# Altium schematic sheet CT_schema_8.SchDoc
size 278 x 170 mm
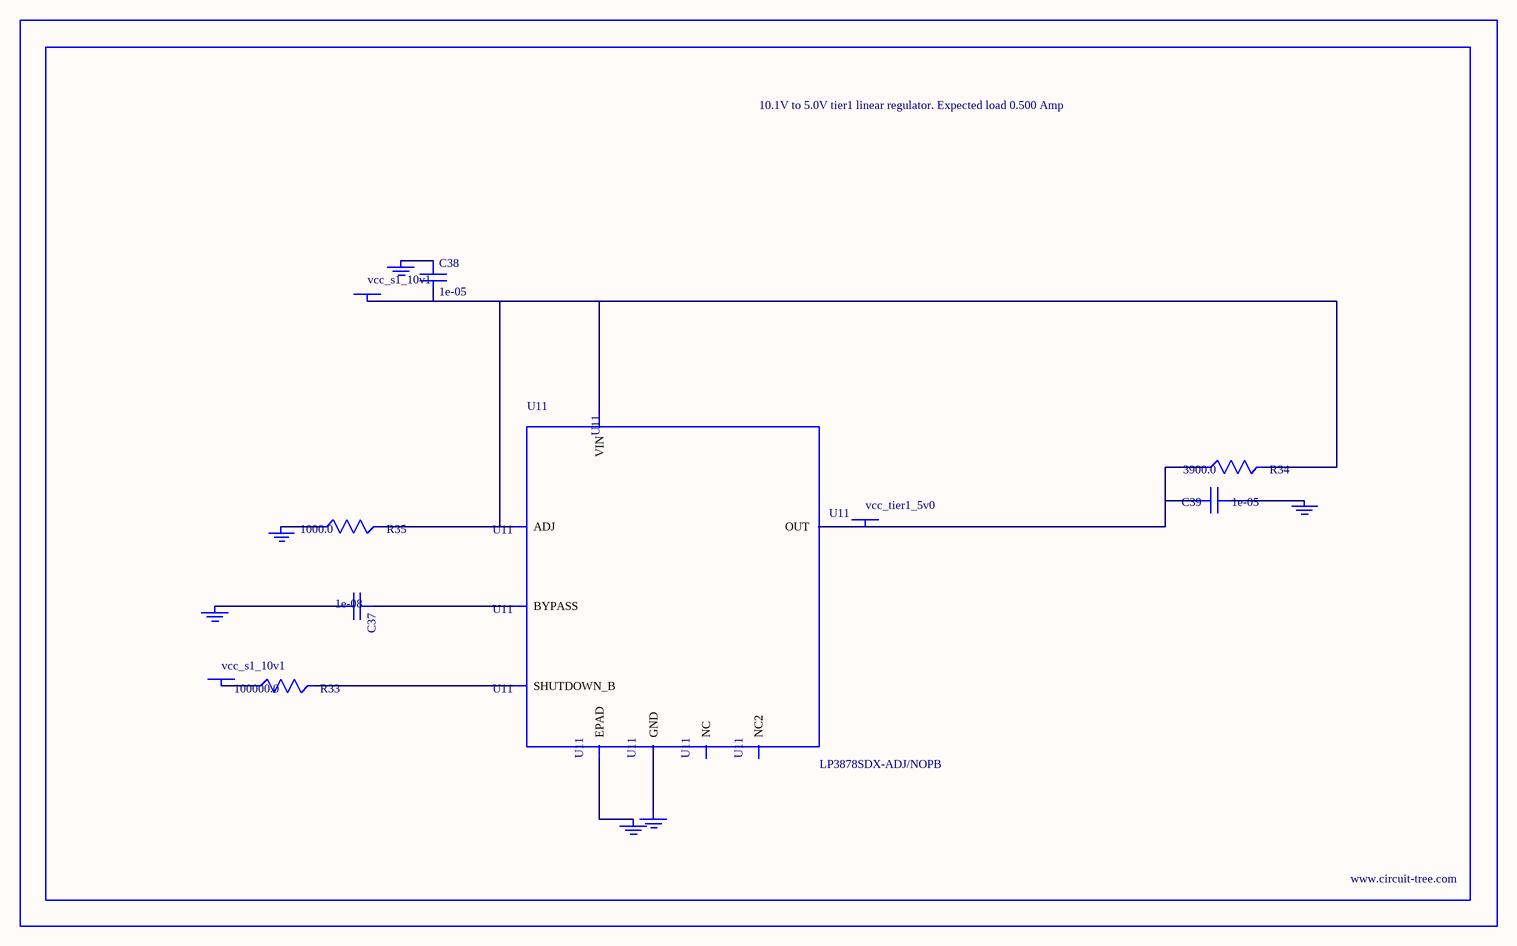
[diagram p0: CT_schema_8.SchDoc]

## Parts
BORDER7  (no value)
C37  1e-08  [C0402]
C38  1e-05  [C1206]
C39  1e-05  [C1210]
GND_INSTANCE_7_0  (no value)
GND_INSTANCE_7_1  (no value)
GND_INSTANCE_7_2  (no value)
GND_INSTANCE_7_3  (no value)
GND_INSTANCE_7_4  (no value)
GND_INSTANCE_7_5  (no value)
POWER_INSTANCE_7_0  vcc_s1_10v1
POWER_INSTANCE_7_1  vcc_s1_10v1
POWER_INSTANCE_7_2  vcc_tier1_5v0
R33  100000.0  [R0603]
R34  3900.0  [R0603]
R35  1000.0  [R0603]
U11  LP3878SDX-ADJ/NOPB  [WSON-8]

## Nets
NetC37_1: C37.1 U11.1(BYPASS)
NetC37_2: C37.2 GND_INSTANCE_7_0.0(GND)
NetC38_1: C38.1 GND_INSTANCE_7_1.0(GND)
NetC38_2: C38.2 POWER_INSTANCE_7_0.0(PWR) R34.2 R35.2 U11.4(VIN) U11.6(ADJ)
NetC39_1: C39.1 GND_INSTANCE_7_2.0(GND)
NetC39_2: C39.2 POWER_INSTANCE_7_2.0(PWR) R34.1 U11.5(OUT)
NetGND_INSTANCE_7_3_0: GND_INSTANCE_7_3.0(GND) R35.1
NetGND_INSTANCE_7_4_0: GND_INSTANCE_7_4.0(GND) U11.PAD(EPAD)
NetGND_INSTANCE_7_5_0: GND_INSTANCE_7_5.0(GND) U11.3(GND)
NetPOWER_INSTANCE_7_1_0: POWER_INSTANCE_7_1.0(PWR) R33.1
NetR33_2: R33.2 U11.8(SHUTDOWN_B)

Not connected (* = marked no-connect by the designer): U11 2(NC) 7(NC2)

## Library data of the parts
BORDER7 = BORDER_PAGE7
C37 = C0402C103K3RAC
C38 = C1206C106K3RACTU
C39 = GRM32DR61E106MA12L
GND_INSTANCE_7_0-GND_INSTANCE_7_5 = GND
POWER_INSTANCE_7_0-POWER_INSTANCE_7_2 = PWR
R33 = RC0603JR-07100KL
R34 = RC0603JR-073K9L
R35 = RC0603JR-071KL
